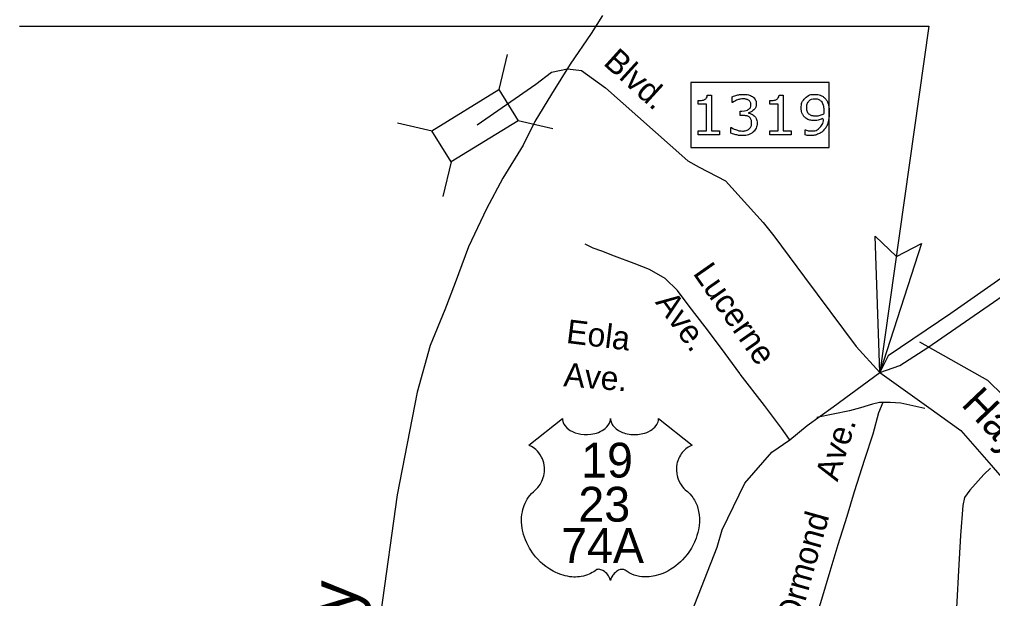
# Model space of a CAD drawing. Extents: x 925297 to 940193, y 663541 to 689899.
# Drawn here: x 927167 to 927782, y 688356 to 688722 of the extents above; entities that cross this region are included whole.
import ezdxf

# ---------------------------------------------------------------- set-up
doc = ezdxf.new("R2010")
doc.units = 0
for name, color, linetype in [('Default', 7, 'Continuous'), ('Exist Horizontal Alignment Tick Large', 7, 'Continuous'), ('Old_Level_28', 7, 'Continuous'), ('Prop Terminator CELL', 7, 'Continuous'), ('Sheet Title CELL', 7, 'Continuous')]:
    doc.layers.add(name, color=color, linetype=linetype)

# ---------------------------------------------------------------- blocks, each defined once
blk = doc.blocks.new('Terminator')
at = {"layer": 'Prop Terminator CELL'}
blk.add_lwpolyline([(-9, 1.55), (0, 0), (-9.05, -1.6), (-7.9, 0)], close=True, dxfattribs=at)

msp = doc.modelspace()

# ---------------------------------------------------------------- linework, layer by layer
at = {"layer": 'Default'}
for p, q in [((927475.01, 688699.71), (927469.79, 688677.68)), ((927427.82, 688651.29), (927405.8, 688656.51)), ((927503.98, 688652.76), (927481.96, 688657.98)), ((927591.07, 688641.08), (927678.63, 688641.08)), ((927439.71, 688632.03), (927434.5, 688610.01))]:
    msp.add_line(p, q, dxfattribs=at)
for points in [[(928236.88, 688765.2), (928197.65, 688760.37), (928148.73, 688752.64), (928111.1, 688742.35), (928064.45, 688727.61), (928020.95, 688711.49), (927997.19, 688699.27), (927957.24, 688676.7), (927843.22, 688597.56), (927755.38, 688536.1), (927715.75, 688509.34), (927710.65, 688498.84)], [(927710.65, 688498.84), (927723.22, 688503.35), (927740.94, 688514.64), (927877, 688608.54), (927962.31, 688666.83), (928028.27, 688701.9), (928109.47, 688731.89), (928131.56, 688737.94), (928198.26, 688751.16), (928238.86, 688753.74)], [(927535.31, 688724.53), (927528.13, 688713.13), (927514.88, 688693.7), (927503.08, 688674.77), (927492.49, 688657.39), (927485.11, 688642.58), (927472.28, 688621.57), (927462.12, 688602.35), (927450.74, 688578.16), (927442.35, 688555.48), (927435.71, 688538.55), (927426.53, 688515.9), (927418.32, 688486.39), (927405.54, 688421.54), (927395.33, 688347.45)], [(927456.2, 688655.31), (927493.14, 688681.11), (927503.21, 688688.6), (927513.19, 688690.71)], [(927513.19, 688690.71), (927522.08, 688689.69), (927537.28, 688678.68), (927589.17, 688632.65), (927596.36, 688628.7), (927613.13, 688619.96), (927636.92, 688593.62), (927643.58, 688585.26), (927662.95, 688559.14), (927695.54, 688515.31), (927710.65, 688498.84)], [(927591.07, 688641.08), (927678.63, 688641.08), (927678.63, 688682.08), (927591.07, 688682.08), (927591.07, 688641.08)], [(927601.57, 688674.16), (927604.17, 688674.16), (927604.17, 688651.63), (927609.27, 688651.63), (927609.27, 688649.08)], [(927617.4, 688669.53), (927617.24, 688669.53), (927617.24, 688673.03)], [(927646.88, 688674.16), (927649.48, 688674.16), (927649.48, 688651.63), (927654.59, 688651.63), (927654.59, 688649.08)], [(927609.27, 688649.08), (927595.74, 688649.08), (927595.74, 688651.63), (927600.95, 688651.63), (927600.95, 688668.39), (927595.74, 688668.39), (927595.74, 688670.67)], [(927654.59, 688649.08), (927641.06, 688649.08), (927641.06, 688651.63), (927646.26, 688651.63), (927646.26, 688668.39), (927641.06, 688668.39), (927641.06, 688670.67)], [(927623.81, 688661.26), (927622.3, 688661.26), (927622.3, 688664.04), (927623.47, 688664.04)], [(927627.53, 688662.99), (927627.53, 688662.75)], [(927616.52, 688650.13), (927616.52, 688653.63), (927616.77, 688653.63)], [(927663.37, 688648.98), (927663.37, 688652.2), (927663.53, 688652.2)], [(927622.14, 688498.12), (927610.61, 688513.99), (927600.29, 688527.67), (927590.13, 688540.76), (927582.76, 688550.57), (927574.89, 688558.2), (927565.12, 688563.91), (927555.35, 688567.65), (927542.85, 688572.38), (927534.94, 688575.58), (927529.39, 688577.52), (927524.42, 688580.03)], [(927836.14, 688381.91), (927837.25, 688389.16), (927840.21, 688406.53), (927843.89, 688424.72), (927842.09, 688431.22), (927837.54, 688437.35), (927830.74, 688444.2), (927820.63, 688453.92), (927808.38, 688465.01), (927798.66, 688474.38), (927791.15, 688481.96), (927788.44, 688484.4), (927778.87, 688493.9), (927735.86, 688517.98)], [(927591.84, 688347.72), (927607.69, 688388.45), (927610.91, 688399.42), (927625.34, 688428.93), (927642.42, 688448.6), (927653.69, 688456.34), (927664.65, 688465.37), (927681.01, 688477.23), (927710.65, 688498.84)], [(927653.54, 688456.43), (927648.4, 688463.71), (927637.72, 688478.04), (927622.34, 688497.84), (927622.14, 688498.12)], [(927710.65, 688498.84), (927741.52, 688476.83), (927761.69, 688462.14), (927781, 688440.26), (927807.19, 688409.66)], [(927712.46, 688479.88), (927709.71, 688473.43), (927706.07, 688459.81), (927700.87, 688443.87), (927694.3, 688423.48), (927689.68, 688407.88), (927684.02, 688390.05), (927678.89, 688373.19), (927673.64, 688355.41), (927668.57, 688339.18), (927666.26, 688329.54), (927665.91, 688318.63), (927667.61, 688305.53), (927670.65, 688287.95), (927673.95, 688274.17), (927676.34, 688259.83), (927677.3, 688251.84), (927676.93, 688246.95)], [(927712.46, 688479.88), (927710.41, 688479.86), (927705.87, 688478.94), (927698.3, 688476.57), (927691.33, 688474.64), (927670.74, 688470.49)], [(927738.92, 688476.03), (927723.82, 688479.44), (927717.2, 688479.91), (927712.46, 688479.88)], [(927780.59, 688438.49), (927776.24, 688434.35), (927767.51, 688424.42), (927764.03, 688419.9), (927762.91, 688414.82), (927761.61, 688395.79), (927760.33, 688373.72), (927759.24, 688353.91), (927758.04, 688333.09), (927756.95, 688312.44), (927756.87, 688300.05), (927756.12, 688254.29), (927751.73, 688204.8), (927750.41, 688183.29), (927748.19, 688158.95), (927745.23, 688137.21), (927745.44, 688136.29)]]:
    msp.add_lwpolyline(points, dxfattribs=at)
for points in [[(927481.96, 688657.98), (927439.77, 688631.94), (927427.61, 688651.65), (927469.79, 688677.68)], [(927509.97, 688469.79), (927510.03, 688468.91), (927510.24, 688467.86), (927510.4, 688467.32), (927510.89, 688466.29), (927511.7, 688465.08), (927512.82, 688463.88), (927514.09, 688462.84), (927514.94, 688462.29), (927516.39, 688461.51), (927518.04, 688460.82), (927519.87, 688460.29), (927521.74, 688459.91), (927523.78, 688459.69), (927525.81, 688459.65), (927527.99, 688459.81), (927530.4, 688460.28), (927531.52, 688460.57), (927532.76, 688460.99), (927533.92, 688461.47), (927535.18, 688462.15), (927536.2, 688462.8), (927537, 688463.38), (927538.13, 688464.46), (927539.02, 688465.58), (927539.4, 688466.21), (927539.73, 688466.81), (927540.17, 688468.09), (927540.3, 688468.66), (927540.39, 688469.83), (927540.46, 688468.84), (927540.56, 688468.23), (927540.73, 688467.63), (927540.98, 688466.99), (927541.43, 688466.08), (927541.93, 688465.33), (927542.88, 688464.21), (927543.47, 688463.66), (927544.01, 688463.22), (927545.45, 688462.23), (927547.14, 688461.37), (927547.97, 688461.01), (927548.82, 688460.71), (927549.9, 688460.38), (927551.02, 688460.12), (927552.12, 688459.93), (927553.25, 688459.76), (927554.41, 688459.68), (927555.35, 688459.65), (927556.51, 688459.66), (927557.57, 688459.73), (927558.66, 688459.85), (927559.87, 688460.05), (927560.84, 688460.27), (927562.12, 688460.61), (927563.27, 688461.02), (927564.29, 688461.46), (927565.61, 688462.15), (927566.67, 688462.82), (927567.45, 688463.44), (927568.38, 688464.3), (927569.26, 688465.32), (927569.77, 688466.06), (927570.14, 688466.82), (927570.48, 688467.63), (927570.68, 688468.48), (927570.79, 688469.22), (927570.81, 688469.85), (927592.06, 688452.92), (927591.56, 688452.73), (927590.41, 688452.16), (927589.49, 688451.62), (927588.03, 688450.59), (927587.4, 688450.03), (927586.77, 688449.44), (927586.19, 688448.81), (927585.69, 688448.22), (927585.07, 688447.37), (927584.52, 688446.51), (927583.98, 688445.57), (927583.58, 688444.75), (927582.93, 688443.05), (927582.62, 688441.97), (927582.41, 688441.05), (927582.16, 688439.15), (927582.1, 688438.25), (927582.1, 688437.36), (927582.15, 688436.41), (927582.24, 688435.51), (927582.4, 688434.57), (927582.55, 688433.74), (927582.82, 688432.72), (927583.19, 688431.54), (927583.66, 688430.4), (927584.63, 688428.55), (927585.88, 688426.67), (927586.77, 688425.61), (927587.65, 688424.71), (927588.96, 688423.6), (927589.67, 688422.98), (927590.49, 688422.16), (927591.82, 688420.61), (927592.36, 688419.89), (927592.9, 688419.07), (927593.41, 688418.23), (927593.91, 688417.32), (927594.31, 688416.53), (927595.06, 688414.71), (927595.6, 688412.94), (927595.85, 688412.01), (927596.25, 688409.93), (927596.4, 688408.9), (927596.56, 688406.86), (927596.57, 688404.4), (927596.38, 688402.06), (927595.94, 688399.34), (927595.58, 688397.71), (927595.02, 688395.81), (927594.48, 688394.16), (927593.51, 688391.74), (927592.65, 688389.98), (927591.53, 688387.92), (927590.76, 688386.68), (927589.87, 688385.35), (927588.75, 688383.81), (927587.45, 688382.18), (927585.88, 688380.46), (927584.61, 688379.19), (927582.95, 688377.71), (927581.95, 688376.88), (927580.52, 688375.8), (927578.56, 688374.49), (927576.63, 688373.38), (927574.98, 688372.54), (927573.53, 688371.91), (927571.64, 688371.19), (927568.51, 688370.32), (927567.36, 688370.09), (927566.01, 688369.89), (927564.74, 688369.76), (927563.51, 688369.68), (927561.85, 688369.68), (927560.21, 688369.81), (927558.65, 688370.04), (927557.03, 688370.38), (927555.34, 688370.88), (927553.8, 688371.48), (927552.24, 688372.25), (927549.61, 688373.9), (927548.85, 688374.31), (927548.43, 688374.42), (927547.41, 688374.47), (927546.46, 688374.27), (927545.48, 688373.88), (927544.89, 688373.57), (927544.1, 688373.05), (927543.5, 688372.57), (927542.77, 688371.88), (927542.27, 688371.3), (927541.89, 688370.85), (927541.15, 688369.68), (927540.88, 688369.13), (927540.61, 688368.42), (927540.36, 688367.36), (927540.03, 688368.69), (927539.64, 688369.57), (927539.19, 688370.32), (927538.72, 688370.99), (927537.98, 688371.84), (927537.31, 688372.48), (927536.51, 688373.14), (927535.65, 688373.65), (927534.97, 688374), (927534.34, 688374.24), (927533.58, 688374.43), (927532.95, 688374.48), (927532.43, 688374.47), (927531.73, 688374.31), (927530.76, 688373.62), (927529.85, 688372.99), (927528.86, 688372.37), (927527.68, 688371.74), (927526.82, 688371.34), (927525.79, 688370.94), (927524.58, 688370.54), (927523.28, 688370.2), (927521.93, 688369.94), (927520.75, 688369.75), (927519.49, 688369.63), (927518.34, 688369.6), (927517.15, 688369.61), (927516.03, 688369.7), (927514.74, 688369.81), (927513.13, 688370.05), (927511.8, 688370.35), (927510.4, 688370.73), (927508.95, 688371.18), (927507.41, 688371.77), (927505.48, 688372.61), (927504.13, 688373.3), (927502.01, 688374.52), (927499.53, 688376.24), (927497.65, 688377.76), (927496.27, 688379), (927494.25, 688381.06), (927493.07, 688382.41), (927491.2, 688384.82), (927490.01, 688386.56), (927489.24, 688387.85), (927488.11, 688389.91), (927487.49, 688391.2), (927486.68, 688393.08), (927486.05, 688394.8), (927485.52, 688396.44), (927485.24, 688397.48), (927484.84, 688399.3), (927484.59, 688400.59), (927484.36, 688402.36), (927484.22, 688404.24), (927484.2, 688405.96), (927484.24, 688407.39), (927484.41, 688409.06), (927484.69, 688410.83), (927485.03, 688412.35), (927485.34, 688413.44), (927485.79, 688414.77), (927486.38, 688416.24), (927487.09, 688417.65), (927487.76, 688418.82), (927488.6, 688420.07), (927489.43, 688421.14), (927490.51, 688422.32), (927491.64, 688423.4), (927492.68, 688424.24), (927493.91, 688425.45), (927494.55, 688426.18), (927495.32, 688427.2), (927495.94, 688428.14), (927496.43, 688428.98), (927497.07, 688430.22), (927497.46, 688431.15), (927497.95, 688432.58), (927498.2, 688433.59), (927498.45, 688434.88), (927498.61, 688436.1), (927498.67, 688437.62), (927498.64, 688438.88), (927498.47, 688440.35), (927498.2, 688441.75), (927497.86, 688442.98), (927497.34, 688444.39), (927496.85, 688445.42), (927496.04, 688446.81), (927495.13, 688448.11), (927494.2, 688449.16), (927493.26, 688450.1), (927492.35, 688450.81), (927491.49, 688451.42), (927490.41, 688452.08), (927489.37, 688452.59), (927488.72, 688452.85)]]:
    msp.add_lwpolyline(points, close=True, dxfattribs=at)
for points in [[(927595.74, 688670.67), (927596.8, 688670.67), (927598.01, 688670.85), (927599.22, 688671.02), (927599.84, 688671.36), (927600.61, 688671.78), (927601.06, 688672.43), (927601.5, 688673.07), (927601.57, 688674.16)], [(927617.24, 688673.03), (927618.43, 688673.62), (927620.42, 688674.12), (927622.41, 688674.61), (927624.28, 688674.61), (927626.11, 688674.61), (927627.51, 688674.28), (927628.9, 688673.94), (927630.03, 688673.2), (927631.24, 688672.39), (927631.86, 688671.25), (927632.48, 688670.11), (927632.48, 688668.58), (927632.48, 688666.5), (927631.01, 688664.94), (927629.54, 688663.39), (927627.53, 688662.99)], [(927641.06, 688670.67), (927642.11, 688670.67), (927643.32, 688670.85), (927644.53, 688671.02), (927645.15, 688671.36), (927645.92, 688671.78), (927646.37, 688672.43), (927646.81, 688673.07), (927646.88, 688674.16)], [(927663.53, 688652.2), (927664.02, 688651.95), (927664.91, 688651.72), (927665.8, 688651.49), (927666.89, 688651.49), (927670.59, 688651.49), (927672.7, 688653.71), (927674.8, 688655.94), (927675.14, 688659.85), (927673.58, 688658.91), (927672.21, 688658.5), (927670.83, 688658.1), (927669.2, 688658.1), (927667.66, 688658.1), (927666.41, 688658.4), (927665.16, 688658.71), (927663.91, 688659.58), (927662.43, 688660.61), (927661.68, 688662.19), (927660.94, 688663.77), (927660.94, 688665.97), (927660.94, 688669.8), (927663.46, 688672.21), (927665.97, 688674.61), (927669.6, 688674.61), (927671.41, 688674.61), (927672.96, 688674.05), (927674.5, 688673.48), (927675.66, 688672.36), (927677.09, 688670.96), (927677.86, 688668.77), (927678.63, 688666.58), (927678.63, 688663.1)], [(927623.47, 688664.04), (927626.03, 688664.04), (927627.55, 688665.11), (927629.07, 688666.18), (927629.07, 688668.23), (927629.07, 688669.14), (927628.69, 688669.82), (927628.3, 688670.5), (927627.61, 688670.94), (927626.89, 688671.38), (927626.06, 688671.54), (927625.24, 688671.71), (927624.2, 688671.71), (927622.6, 688671.71), (927620.8, 688671.14), (927619, 688670.57), (927617.4, 688669.53)], [(927675.22, 688663.83), (927675.22, 688666.43), (927674.69, 688668.01), (927674.15, 688669.59), (927673.21, 688670.47), (927672.42, 688671.22), (927671.52, 688671.55), (927670.61, 688671.88), (927669.56, 688671.88), (927667.15, 688671.88), (927665.75, 688670.36), (927664.35, 688668.85), (927664.35, 688666.12), (927664.35, 688664.52), (927664.8, 688663.51), (927665.25, 688662.51), (927666.32, 688661.75), (927667.08, 688661.23), (927667.98, 688661.05), (927668.89, 688660.88), (927669.99, 688660.88), (927671.3, 688660.88), (927672.64, 688661.23), (927673.98, 688661.58), (927675.16, 688662.25), (927675.17, 688662.61), (927675.2, 688662.95), (927675.22, 688663.29), (927675.22, 688663.83)], [(927631.14, 688661.12), (927631.95, 688660.4), (927632.47, 688659.31), (927632.99, 688658.21), (927632.99, 688656.48), (927632.99, 688654.77), (927632.37, 688653.34), (927631.75, 688651.91), (927630.62, 688650.85), (927629.36, 688649.68), (927627.66, 688649.11), (927625.96, 688648.55), (927623.93, 688648.55), (927621.84, 688648.55), (927619.83, 688649.04), (927617.81, 688649.54), (927616.52, 688650.13)], [(927616.77, 688653.63), (927618.2, 688652.69), (927620.14, 688652.07), (927622.07, 688651.45), (927623.87, 688651.45), (927624.93, 688651.45), (927626.12, 688651.8), (927627.31, 688652.15), (927628.05, 688652.85), (927628.83, 688653.59), (927629.2, 688654.48), (927629.58, 688655.37), (927629.58, 688656.73), (927629.58, 688658.08), (927629.15, 688658.97), (927628.72, 688659.85), (927627.97, 688660.35), (927627.21, 688660.88), (927626.13, 688661.07), (927625.06, 688661.26), (927623.81, 688661.26)], [(927627.53, 688662.75), (927628.34, 688662.62), (927629.38, 688662.19), (927630.42, 688661.76), (927631.14, 688661.12)], [(927678.63, 688663.1), (927678.63, 688659.82), (927677.88, 688657.15), (927677.14, 688654.47), (927675.63, 688652.59), (927674.1, 688650.67), (927671.8, 688649.63), (927669.5, 688648.59), (927666.39, 688648.59), (927665.52, 688648.59), (927664.74, 688648.68), (927663.97, 688648.78), (927663.37, 688648.98)]]:
    msp.add_open_spline(points, degree=3, dxfattribs=at)
at = {"layer": 'Exist Horizontal Alignment Tick Large'}
for p, q in [((927166.96, 688717.79), (927741.54, 688717.79)), ((927741.54, 688717.79), (927710.65, 688498.84))]:
    msp.add_line(p, q, dxfattribs=at)
at = {"layer": 'Old_Level_28'}
msp.add_lwpolyline([(927710.65, 688498.84), (927741.52, 688476.83), (927761.69, 688462.14), (927781, 688440.26), (927807.19, 688409.66)], dxfattribs=at)

# ---------------------------------------------------------------- block references
at = {"layer": 'Sheet Title CELL', "xscale": 9.375000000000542, "yscale": 9.375000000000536, "rotation": -98.02910329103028}
msp.add_blockref('Terminator', (927710.65, 688498.84), dxfattribs=at)

# ---------------------------------------------------------------- texts
at = {"layer": 'Default'}
for s, height, rotation, p in [('Blvd.', 15, 317.76956, (927535.26, 688693.81)), ('Lucerne', 15, 304.95765, (927592.09, 688561.5)), ('Ave.', 15, 305.96947, (927568.28, 688543.17)), ('Eola', 15, 352.99264, (927511.96, 688517.6)), ('Ave.', 15, 355.34187, (927510.39, 688490.21)), ('Haywood', 19, 313.59519, (927761.36, 688478.3)), ('Ave.', 15, 72.64126, (927683.81, 688429.45)), ('Ormond', 15, 74.36337, (927659.24, 688338.59)), ('Railway', 30, 87.41408, (927374.48, 688226.23))]:
    msp.add_text(s, height=height, rotation=rotation, dxfattribs=at).set_placement(p)
for s, p in [('19', (927521.85, 688432.47)), ('23', (927520.08, 688404.61)), ('74A', (927509.21, 688378.52))]:
    msp.add_text(s, height=22, dxfattribs=at).set_placement(p)

doc.saveas('drawing.dxf')
